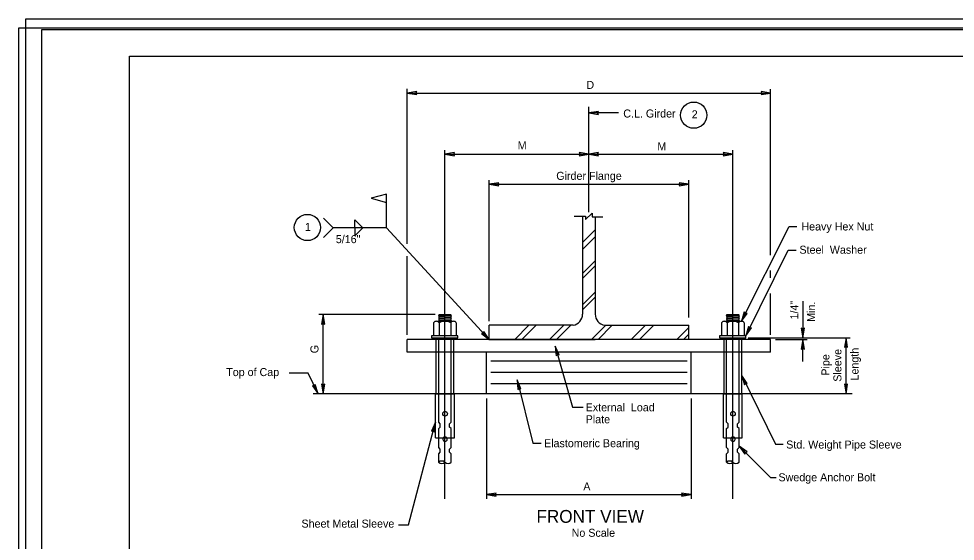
# Model space of a CAD drawing. Extents: x -194 to 226, y 505 to 725.
# Drawn here: x -193.6 to -47.4, y 643.6 to 725.2 of the extents above; entities that cross this region are included whole.
import ezdxf

# ---------------------------------------------------------------- set-up
doc = ezdxf.new("R2010")
doc.units = 0
for name, color, linetype in [('border', 7, 'Continuous'), ('Border 2660-Hwy18 - Level 62', 7, 'Continuous'), ('Border 2660-Hwy18 - Level 63', 7, 'Continuous'), ('Level 20', 7, 'Continuous'), ('Level 21', 7, 'Continuous'), ('Level 31', 7, 'Continuous'), ('Level 40', 7, 'Continuous'), ('Level 41', 7, 'Continuous'), ('Level 42', 7, 'Continuous'), ('Level 43', 7, 'Continuous'), ('Level 62 PDF', 7, 'Continuous')]:
    doc.layers.add(name, color=color, linetype=linetype)

msp = doc.modelspace()

# ---------------------------------------------------------------- linework, layer by layer
at = {"layer": 'border'}
for p, q in [((-176.33, 719.31), (143.78, 719.31)), ((-176.33, 513.86), (-176.33, 719.31))]:
    msp.add_line(p, q, dxfattribs=at)
at = {"layer": 'Border 2660-Hwy18 - Level 62'}
msp.add_lwpolyline([(-192.53, 725.17), (148.65, 725.17), (148.65, 507.07), (-192.53, 507.07)], close=True, dxfattribs=at)
at = {"layer": 'Border 2660-Hwy18 - Level 63'}
msp.add_lwpolyline([(-193.64, 723.74), (146.35, 723.74), (146.35, 510.04), (-193.64, 510.04)], close=True, dxfattribs=at)
at = {"layer": 'Level 20'}
for p, q in [((-104.63, 695), (-104.63, 711.42)), ((-127.1, 650.25), (-127.1, 704.67)), ((-82.15, 650.25), (-82.15, 704.67))]:
    msp.add_line(p, q, dxfattribs=at)
at = {"layer": 'Level 21'}
msp.add_line((-63.52, 666.64), (-147.67, 666.64), dxfattribs=at)
at = {"layer": 'Level 31'}
for p, q in [((-105.61, 694.36), (-105.61, 679.08)), ((-103.64, 694.26), (-103.64, 679.08)), ((-128.02, 679), (-128.08, 678.89)), ((-128.08, 678.89), (-126.12, 678.89)), ((-128.08, 678.87), (-128.08, 678.89)), ((-126.16, 678.79), (-128.08, 678.88)), ((-126.16, 678.59), (-128.08, 678.68)), ((-126.16, 678.41), (-128.08, 678.5)), ((-128.02, 679), (-126.2, 679)), ((-126.2, 679), (-126.12, 678.89)), ((-126.12, 678.87), (-126.12, 678.89)), ((-83.07, 679), (-83.14, 678.89)), ((-83.14, 678.89), (-81.17, 678.89)), ((-83.14, 678.87), (-83.14, 678.89)), ((-81.21, 678.79), (-83.14, 678.88)), ((-81.21, 678.59), (-83.14, 678.68)), ((-81.21, 678.41), (-83.14, 678.5)), ((-83.07, 679), (-81.25, 679)), ((-81.25, 679), (-81.17, 678.89)), ((-81.17, 678.87), (-81.17, 678.89)), ((-128.87, 677.71), (-128.87, 675.67)), ((-128.44, 677.95), (-125.75, 677.95)), ((-126.16, 678.22), (-128.08, 678.32)), ((-126.16, 678.04), (-128.08, 678.13)), ((-128.01, 677.71), (-128.01, 675.67)), ((-126.2, 677.71), (-126.2, 675.67)), ((-125.33, 677.71), (-125.33, 675.67)), ((-107.08, 677.32), (-120.21, 677.32)), ((-120.21, 675.09), (-120.21, 677.32)), ((-102.17, 677.32), (-89.04, 677.32)), ((-89.04, 675.09), (-89.04, 677.32)), ((-83.92, 677.71), (-83.92, 675.67)), ((-83.49, 677.95), (-80.8, 677.95)), ((-81.21, 678.22), (-83.14, 678.32)), ((-81.21, 678.04), (-83.14, 678.13)), ((-83.06, 677.71), (-83.06, 675.67)), ((-81.25, 677.71), (-81.25, 675.67)), ((-80.38, 677.71), (-80.38, 675.67)), ((-76.25, 675.09), (-133, 675.09)), ((-133, 673.12), (-133, 675.09)), ((-128.48, 673.12), (-128.48, 675.38)), ((-128.2, 675.38), (-126.03, 675.38)), ((-128.08, 673.12), (-128.08, 675.38)), ((-126.12, 673.12), (-126.12, 675.38)), ((-125.72, 673.12), (-125.72, 675.38)), ((-120.21, 675.09), (-103.64, 675.09)), ((-89.04, 675.09), (-105.61, 675.09)), ((-83.53, 673.12), (-83.53, 675.38)), ((-83.25, 675.38), (-81.08, 675.38)), ((-83.14, 673.12), (-83.14, 675.38)), ((-81.17, 673.12), (-81.17, 675.38)), ((-80.77, 673.12), (-80.77, 675.38)), ((-76.25, 673.12), (-76.25, 675.09)), ((-76.25, 673.12), (-133, 673.12)), ((-128.48, 666.64), (-128.48, 673.12)), ((-128.08, 666.64), (-128.08, 673.12)), ((-126.12, 666.64), (-126.12, 673.12)), ((-125.72, 666.64), (-125.72, 673.12)), ((-120.61, 666.64), (-120.61, 673.12)), ((-88.65, 666.64), (-88.65, 673.12)), ((-83.53, 666.64), (-83.53, 673.12)), ((-83.14, 666.64), (-83.14, 673.12)), ((-81.17, 666.64), (-81.17, 673.12)), ((-80.77, 666.64), (-80.77, 673.12)), ((-119.96, 671.79), (-89.29, 671.79)), ((-119.96, 670.02), (-89.29, 670.02)), ((-119.96, 668.25), (-89.29, 668.25)), ((-128.57, 659.75), (-128.57, 666.64)), ((-128.57, 666.64), (-125.62, 666.64)), ((-128.48, 666.64), (-125.72, 666.64)), ((-128.08, 662.22), (-128.08, 666.64)), ((-126.12, 662.22), (-126.12, 666.64)), ((-125.62, 659.75), (-125.62, 666.64)), ((-83.62, 659.75), (-83.62, 666.64)), ((-83.62, 666.64), (-80.67, 666.64)), ((-83.53, 666.64), (-80.77, 666.64)), ((-83.14, 662.22), (-83.14, 666.64)), ((-81.17, 662.22), (-81.17, 666.64)), ((-80.67, 659.75), (-80.67, 666.64)), ((-127.84, 661.95), (-128.08, 662.22)), ((-128.08, 661.19), (-127.84, 661.44)), ((-128.08, 659.75), (-128.08, 661.19)), ((-127.84, 661.44), (-127.84, 661.95)), ((-126.37, 661.95), (-126.12, 662.22)), ((-126.37, 661.44), (-126.37, 661.95)), ((-126.12, 661.19), (-126.37, 661.44)), ((-126.12, 659.75), (-126.12, 661.19)), ((-82.89, 661.95), (-83.14, 662.22)), ((-83.14, 661.19), (-82.89, 661.44)), ((-83.14, 659.75), (-83.14, 661.19)), ((-82.89, 661.44), (-82.89, 661.95)), ((-81.42, 661.95), (-81.17, 662.22)), ((-81.42, 661.44), (-81.42, 661.95)), ((-81.17, 661.19), (-81.42, 661.44)), ((-81.17, 659.75), (-81.17, 661.19)), ((-128.57, 659.75), (-125.62, 659.75)), ((-128.08, 658.26), (-128.08, 659.75)), ((-126.12, 658.26), (-126.12, 659.75)), ((-83.62, 659.75), (-80.67, 659.75)), ((-83.14, 658.26), (-83.14, 659.75)), ((-81.17, 658.26), (-81.17, 659.75)), ((-127.84, 658.01), (-128.08, 658.26)), ((-127.84, 657.51), (-127.84, 658.01)), ((-126.37, 658.01), (-126.12, 658.26)), ((-126.37, 657.51), (-126.37, 658.01)), ((-82.89, 658.01), (-83.14, 658.26)), ((-82.89, 657.51), (-82.89, 658.01)), ((-81.42, 658.01), (-81.17, 658.26)), ((-81.42, 657.51), (-81.42, 658.01)), ((-128.08, 657.24), (-127.84, 657.51)), ((-128.08, 655.95), (-128.08, 657.24)), ((-126.12, 657.24), (-126.37, 657.51)), ((-126.12, 655.95), (-126.12, 657.24)), ((-83.14, 657.24), (-82.89, 657.51)), ((-83.14, 655.95), (-83.14, 657.24)), ((-81.17, 657.24), (-81.42, 657.51)), ((-81.17, 655.95), (-81.17, 657.24))]:
    msp.add_line(p, q, dxfattribs=at)
for points in [[(-128.08, 678.87), (-128.05, 678.77), (-128.08, 678.68)], [(-128.08, 678.68), (-128.05, 678.59), (-128.08, 678.5)], [(-128.08, 678.5), (-128.05, 678.41), (-128.08, 678.32)], [(-126.12, 678.87), (-126.16, 678.77), (-126.12, 678.68)], [(-126.12, 678.68), (-126.16, 678.59), (-126.12, 678.5)], [(-126.12, 678.5), (-126.16, 678.41), (-126.12, 678.32)], [(-83.14, 678.87), (-83.1, 678.77), (-83.14, 678.68)], [(-83.14, 678.68), (-83.1, 678.59), (-83.14, 678.5)], [(-83.14, 678.5), (-83.1, 678.41), (-83.14, 678.32)], [(-81.17, 678.87), (-81.21, 678.77), (-81.17, 678.68)], [(-81.17, 678.68), (-81.21, 678.59), (-81.17, 678.5)], [(-81.17, 678.5), (-81.21, 678.41), (-81.17, 678.32)], [(-128.08, 678.32), (-128.05, 678.22), (-128.08, 678.13)], [(-128.08, 678.13), (-128.05, 678.04), (-128.08, 677.95)], [(-126.12, 678.32), (-126.16, 678.22), (-126.12, 678.13)], [(-126.12, 678.13), (-126.16, 678.04), (-126.12, 677.95)], [(-83.14, 678.32), (-83.1, 678.22), (-83.14, 678.13)], [(-83.14, 678.13), (-83.1, 678.04), (-83.14, 677.95)], [(-81.17, 678.32), (-81.21, 678.22), (-81.17, 678.13)], [(-81.17, 678.13), (-81.21, 678.04), (-81.17, 677.95)]]:
    msp.add_lwpolyline(points, dxfattribs=at)
for points in [[(-125.08, 675.38), (-125.08, 675.67), (-129.2, 675.67), (-129.2, 675.38)], [(-80.13, 675.38), (-80.13, 675.67), (-84.25, 675.67), (-84.25, 675.38)]]:
    msp.add_lwpolyline(points, close=True, dxfattribs=at)
for centre in [(-127.08, 663.51), (-82.13, 663.51)]:
    msp.add_circle(centre, 0.356, dxfattribs=at)
for centre, radius, start, end in [((-107.38, 679.06), 1.76, 279.5, 0), ((-101.87, 679.06), 1.76, 180, 260.5), ((-128.44, 677.44), 0.511, 32.004, 147.996), ((-127.1, 676.11), 1.84, 60.5577, 119.4423), ((-125.76, 677.44), 0.511, 32.004, 147.996), ((-83.49, 677.44), 0.511, 32.004, 147.996), ((-82.15, 676.11), 1.84, 60.5577, 119.4423), ((-80.81, 677.44), 0.511, 32.004, 147.996), ((-127.08, 659.56), 0.356, 147.5341, 32.4659), ((-127.08, 659.56), 0.356, 32.4659, 147.5341), ((-82.13, 659.56), 0.356, 147.5341, 32.4659), ((-82.13, 659.56), 0.356, 32.4659, 147.5341), ((-127.59, 655.38), 0.751, 49.0496, 130.9504), ((-127.59, 656.51), 0.751, 229.0496, 310.9504), ((-126.61, 656.51), 0.751, 229.0496, 310.9504), ((-82.64, 655.38), 0.751, 49.0496, 130.9504), ((-82.64, 656.51), 0.751, 229.0496, 310.9504), ((-81.66, 656.51), 0.751, 229.0496, 310.9504)]:
    msp.add_arc(centre, radius, start, end, dxfattribs=at)
at = {"layer": 'Level 40'}
msp.add_circle((-88.26, 710.12), 2.05, dxfattribs=at)
at = {"layer": 'Level 42'}
for p, q in [((-105.61, 690.25), (-103.64, 692.22)), ((-105.61, 689.15), (-103.64, 691.15)), ((-105.61, 685.4), (-103.64, 687.37)), ((-105.61, 684.64), (-103.64, 686.61)), ((-105.61, 680.52), (-103.64, 682.49)), ((-105.61, 679.71), (-103.64, 681.7)), ((-116.21, 675.09), (-113.98, 677.32)), ((-115.08, 675.09), (-112.85, 677.32)), ((-110.78, 675.09), (-108.56, 677.32)), ((-109.68, 675.09), (-107.46, 677.32)), ((-104.23, 675.09), (-101.99, 677.32)), ((-103.2, 675.09), (-100.97, 677.32)), ((-98.01, 675.09), (-95.8, 677.32)), ((-96.72, 675.09), (-94.48, 677.32)), ((-90.92, 675.09), (-89.04, 676.99)), ((-89.87, 675.09), (-89.04, 675.93))]:
    msp.add_line(p, q, dxfattribs=at)
at = {"layer": 'Level 43'}
for p, q in [((-133, 700.65), (-133, 714.21)), ((-133, 713.57), (-76.25, 713.57)), ((-76.25, 701.13), (-76.25, 714.19)), ((-99.98, 710.46), (-104.63, 710.46)), ((-127.1, 704.03), (-104.63, 704.03)), ((-104.63, 704.03), (-82.15, 704.03)), ((-133, 690.01), (-133, 700.65)), ((-76.25, 688.26), (-76.25, 701.13)), ((-120.21, 677.95), (-120.21, 699.98)), ((-120.21, 699.33), (-89.04, 699.33)), ((-89.04, 678.53), (-89.04, 699.98)), ((-136.21, 692.54), (-136.21, 697.81)), ((-144.55, 692.54), (-146.07, 694.06)), ((-141.17, 692.54), (-141.17, 693.8)), ((-141.17, 693.8), (-139.91, 692.54)), ((-144.55, 692.54), (-146.07, 691.02)), ((-141.17, 692.54), (-141.17, 691.28)), ((-141.17, 691.28), (-139.91, 692.54)), ((-133, 675.82), (-133, 688.09)), ((-76.25, 684.74), (-76.25, 685.89)), ((-76.25, 675.82), (-76.25, 682.28)), ((-71.21, 681.09), (-71.21, 675.38)), ((-128.64, 679), (-146.77, 679)), ((-146.12, 666.64), (-146.12, 679)), ((-79.74, 675.38), (-63.84, 675.38)), ((-78.98, 675.38), (-70.46, 675.38)), ((-75.5, 675.09), (-70.57, 675.09)), ((-71.21, 671.66), (-71.21, 675.09)), ((-64.48, 666.64), (-64.48, 675.38)), ((-120.61, 665.89), (-120.61, 650.25)), ((-88.65, 665.89), (-88.65, 650.25)), ((-120.61, 650.89), (-88.65, 650.89))]:
    msp.add_line(p, q, dxfattribs=at)
for points in [[(-133, 713.57), (-131.5, 713.32), (-131.63, 713.57), (-131.5, 713.82)], [(-76.25, 713.57), (-77.75, 713.82), (-77.62, 713.57), (-77.75, 713.32)], [(-104.63, 710.46), (-103.13, 710.21), (-103.26, 710.46), (-103.13, 710.71)], [(-127.1, 704.03), (-125.6, 703.78), (-125.73, 704.03), (-125.6, 704.28)], [(-104.63, 704.03), (-106.13, 704.28), (-106, 704.03), (-106.13, 703.78)], [(-104.63, 704.03), (-103.13, 703.78), (-103.26, 704.03), (-103.13, 704.28)], [(-82.15, 704.03), (-83.65, 704.28), (-83.52, 704.03), (-83.65, 703.78)], [(-120.21, 699.33), (-118.71, 699.08), (-118.84, 699.33), (-118.71, 699.58)], [(-89.04, 699.33), (-90.54, 699.58), (-90.41, 699.33), (-90.54, 699.08)], [(-136.21, 697.81), (-138.63, 697.16), (-136.21, 696.51)], [(-146.12, 679), (-146.37, 677.5), (-146.12, 677.63), (-145.87, 677.5)], [(-80.81, 677.95), (-79.91, 679.17), (-80.2, 679.17), (-80.36, 679.4)], [(-80.13, 675.67), (-79.24, 676.9), (-79.53, 676.89), (-79.69, 677.12)], [(-120.21, 675.09), (-121.04, 676.36), (-121.14, 676.1), (-121.41, 676.03)], [(-71.21, 675.38), (-70.96, 676.88), (-71.21, 676.75), (-71.46, 676.88)], [(-71.21, 675.09), (-71.46, 673.59), (-71.21, 673.72), (-70.96, 673.59)], [(-64.48, 675.38), (-64.73, 673.88), (-64.48, 674.01), (-64.23, 673.88)], [(-109.9, 674.06), (-109.73, 672.55), (-109.52, 672.75), (-109.25, 672.69)], [(-115.84, 668.8), (-115.73, 667.29), (-115.52, 667.47), (-115.24, 667.41)], [(-80.77, 669.47), (-80.34, 668.02), (-80.17, 668.24), (-79.89, 668.24)], [(-146.91, 666.64), (-147.34, 668.1), (-147.51, 667.87), (-147.79, 667.88)], [(-146.12, 666.64), (-145.87, 668.14), (-146.12, 668.01), (-146.37, 668.14)], [(-64.48, 666.64), (-64.23, 668.14), (-64.48, 668.01), (-64.73, 668.14)], [(-128.57, 662.18), (-129.19, 660.79), (-128.92, 660.85), (-128.71, 660.66)], [(-81.17, 658.45), (-80.28, 657.22), (-80.2, 657.48), (-79.93, 657.57)], [(-120.61, 650.89), (-119.11, 650.64), (-119.24, 650.89), (-119.11, 651.14)], [(-88.65, 650.89), (-90.15, 651.14), (-90.02, 650.89), (-90.15, 650.64)]]:
    msp.add_lwpolyline(points, close=True, dxfattribs=at)
for points in [[(-106.94, 694.36), (-105.13, 694.36), (-105.13, 693.81), (-104.11, 694.82), (-104.11, 694.26), (-102.47, 694.26)], [(-120.21, 675.09), (-136.21, 692.54), (-144.55, 692.54)], [(-80.81, 677.95), (-73.34, 692.75), (-72.15, 692.75)], [(-80.13, 675.67), (-73.52, 689.07), (-72.26, 689.07)], [(-109.9, 674.06), (-107.16, 664.55), (-105.52, 664.55)], [(-146.91, 666.64), (-148.47, 669.84), (-151.43, 669.84)], [(-115.84, 668.8), (-113.4, 658.92), (-112.09, 658.91)], [(-80.77, 669.47), (-75.5, 658.75), (-74.31, 658.75)], [(-134.33, 646.17), (-132.79, 646.17), (-128.57, 662.18)], [(-81.17, 658.45), (-76.27, 653.57), (-75.4, 653.57)]]:
    msp.add_lwpolyline(points, dxfattribs=at)
msp.add_circle((-148.57, 692.58), 2.05, dxfattribs=at)
at = {"layer": 'Level 62 PDF'}
msp.add_lwpolyline([(-190.03, 723.5), (151.15, 723.5), (151.15, 505.41), (-190.03, 505.41)], close=True, dxfattribs=at)

# ---------------------------------------------------------------- texts
at = {"layer": 'Level 40'}
for s, p in [('D', (-105.02, 714.22)), ('C.L. Girder', (-99.26, 709.75)), ('2', (-88.57, 709.63)), ('M', (-115.74, 704.76)), ('M', (-93.94, 704.64)), ('Girder Flange', (-109.72, 700.02)), ('1', (-148.96, 692.05)), ('Heavy Hex Nut', (-71.45, 692.12)), ('5/16"', (-144.14, 690.14)), ('Steel  Washer', (-71.75, 688.49)), ('Top of Cap', (-161.25, 669.39)), ('External  Load ', (-105.13, 663.89)), ('Plate', (-105.13, 662.03)), ('Elastomeric Bearing', (-111.63, 658.29)), ('Std. Weight Pipe Sleeve ', (-73.82, 658.08)), ('Swedge Anchor Bolt ', (-75.03, 652.97)), ('A', (-105.5, 651.54)), ('Sheet Metal Sleeve', (-149.5, 645.74)), ('No Scale', (-107.32, 644.31))]:
    msp.add_text(s, height=1.25, dxfattribs=at).set_placement(p)
for s, p in [('1/4"', (-71.93, 678.22)), ('Min.', (-69.3, 677.86)), ('G', (-146.85, 672.95)), ('Pipe', (-67.07, 669.46)), ('Sleeve', (-65.2, 668.51)), ('Length', (-62.53, 668.7))]:
    msp.add_text(s, height=1.25, rotation=90, dxfattribs=at).set_placement(p)
at = {"layer": 'Level 41'}
msp.add_text(' FRONT VIEW ', height=2, dxfattribs=at).set_placement((-113.56, 646.49))

doc.saveas('drawing.dxf')
